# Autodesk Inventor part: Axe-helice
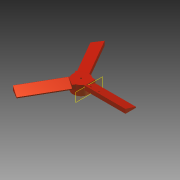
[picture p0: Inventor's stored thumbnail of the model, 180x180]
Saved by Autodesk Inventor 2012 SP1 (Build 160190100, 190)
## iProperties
Created: 2012-06
Part Number: Axe-helice
Material: Default
Document SubType Name: Modeling
Designer: Bruno
Density: 1 g/cm^3
Author: Bruno
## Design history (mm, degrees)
sketch "Esquisse1"
  geometry: C1 r 10 at (0, 0); 1 further point
  constraints: 1 centre point, 1 coincident
  dimensions: "d0" = 20 diameter of C1
extrude "Extrusion1" new body sketch "Esquisse1" distance "d1" = 12; taper "d2" = 0 deg
node "Plan de construction1"
sketch "Esquisse3"
  geometry: A1 r 10 centre (0, 0) between (10, 0) and (10, 0) reference; 3 further points
  constraints: 1 coincident
hole "Perçage1" sketch "Esquisse3" at (0, 0) diameter "d11" = 2; stored, may be unused: countersink angle "d15" = 90 deg, drill point angle "d17" = 118 deg; dims "d12" = 6, "d13" = 4, "d14" = 2, "d16" = 8
sketch "Esquisse5"
  geometry: L1 (-10, 12)-(10, 12) reference; L2 (-10, 0)-(-10, 12) reference; L3 (-10, 0)-(10, 0) reference; L4 (10, 0)-(10, 12) reference; L5 (0, 0)-(0, 12); L6 (-4.887, 12)-(5.179, 8.738); L7 (5.179, 8.738)-(7.589, 7.957); L8 (-4.887, 12)-(-5.183, 12); L9 (-5.183, 6.813)-(7.589, 6.813); L10 (7.589, 6.813)-(7.589, 7.957); L11 (-5.183, 6.813)-(-5.183, 12)
  constraints: 14 end point, 2 parallel, 2 point on line, 1 collinear, 1 midpoint
extrude "Extrusion3" join sketch "Esquisse5" distance "d32" = 50; taper "d33" = 0 deg
sketch "Esquisse6"
  geometry: L1 (12, -5.183)-(12, -4.887) reference; L2 (6.813, -5.183)-(12, -5.183) reference; L3 (6.813, 7.589)-(6.813, -5.183) reference; L4 (7.957, 7.589)-(6.813, 7.589) reference; L5 (12, -4.887)-(7.957, 7.589) reference; L6 (6.813, 7.589)-(12, 7.589); L7 (12, 7.589)-(12, -5.183); L8 (12, -5.183)-(6.813, -5.183); L9 (6.813, -5.183)-(6.813, 7.589); 1 further point
  constraints: 8 end point, 2 parallel, 1 horizontal, 1 perpendicular
extrude "Extrusion4" join sketch "Esquisse6" distance "d34" = 7; taper "d35" = 0 deg
sketch "Esquisse7"
  geometry: L1 (0, -13.115)-(50, -13.115) reference; L2 (4, -8.76)-(4, -10.86); L3 (14, -8.76)-(14, -10.86); 3 further points
  constraints: 4 end point, 2 midpoint, 1 parallel, 1 perpendicular, 2 other
  node "Référence2"
  node "Référence3"
hole "Perçage3" sketch "Esquisse7" diameter "d43" = 2; stored, may be unused: countersink angle "d47" = 90 deg, drill point angle "d49" = 118 deg; dims "d44" = 6, "d45" = 4, "d46" = 2, "d48" = 8
pattern_circular "Réseau circulaire3" dims "d39" = 360 deg
fillet "Congé1" dims "d50" = 2
node "Solide1"
node "Boucle projetée2"
